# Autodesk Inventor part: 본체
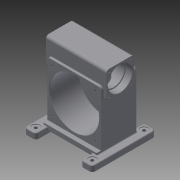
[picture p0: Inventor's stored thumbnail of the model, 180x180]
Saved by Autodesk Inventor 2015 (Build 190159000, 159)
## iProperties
Created: 2025-06
Part Number: 본체
Material: 일반
Document SubType Name: Modeling
Designer: User
Density: 1 g/cm^3
Appearance: 기본값
Author: User
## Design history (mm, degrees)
sketch "스케치4"
  geometry: L1 (-118, 110)-(-78, 110); L2 (-78, 110)-(-78, -110); L3 (-78, -110)-(-118, -110); L4 (-118, -110)-(-118, 110); L5 (78, 110)-(118, 110); L6 (118, 110)-(118, -110); L7 (118, -110)-(78, -110); L8 (78, -110)-(78, 110); 3 further points
  constraints: 16 end point, 4 parallel, 2 horizontal, 2 horizontal alignment, 2 midpoint, 2 perpendicular
  dimensions: "d1" = 40 distance of L2.end L3.end; "d2" = 220 distance of L1.end L2.end; "d3" = 118 distance from line of point (0, 0) L4; "d4" = 40 distance of L6.end L7.end; "d5" = 220 distance of L5.end L6.end; "d6" = 118 distance from line of point (0, 0) L6
extrude "돌출1" new body sketch "스케치4" distance "d7" = 20; taper "d8" = 0 deg
node "작업 평면2"
sketch "스케치5"
  geometry: L1 (93, 70)-(-93, 70); L2 (-93, 70)-(-93, -70); L3 (-93, -70)-(93, -70); L4 (93, -70)-(93, 70); L5 (93, 70)-(-93, -70); L6 (-93, 70)-(93, -70); 1 further point
  constraints: 12 end point, 2 midpoint, 2 parallel, 1 horizontal, 1 perpendicular
  dimensions: "d10" = 186 distance of L3.end L2.end; "d11" = 140 distance of L2.end L1.end
extrude "돌출2" join sketch "스케치5" distance "d12" = 206; taper "d13" = 0 deg
sketch "스케치6"
  geometry: L1 (-15, 206)-(171, 206); L2 (171, 206)-(171, 17); L3 (171, 17)-(-15, 17); L4 (-15, 17)-(-15, 206); 1 further point
  constraints: 8 end point, 2 parallel, 1 horizontal, 1 perpendicular
  dimensions: "d14" = 186 distance of L2.end L3.end; "d15" = 189 distance of L1.end L2.end
extrude "돌출3" cut sketch "스케치6" distance "d16" = 15; taper "d17" = 0 deg
sketch "스케치7"
  geometry: L1 (-15, 206)-(171, 206) reference; L2 (196, -10)-(156, -10) reference; C1 r 86 at (78, 113); 2 further points
  constraints: 1 centre point, 1 midpoint, 1 vertical alignment
  dimensions: "d18" = 172 diameter of C1; "d19" = 123 distance from line of L2 C1.centre
extrude "돌출4" cut sketch "스케치7" distance "d20" = 102; taper "d21" = 0 deg
sketch "스케치8"
  geometry: C1 r 86 at (0, 0) reference; C2 r 31 at (0, 0); 1 further point
  constraints: 1 centre point, 1 coincident
  dimensions: "d22" = 62 diameter of C2
extrude "돌출5" cut sketch "스케치8" distance "d23" = 16; taper "d24" = 0 deg
sketch "스케치9"
  geometry: C1 r 31 at (0, 0) reference; C2 r 27 at (0, 0); 1 further point
  constraints: 1 centre point, 1 coincident
  dimensions: "d25" = 54 diameter of C2
extrude "돌출6" cut sketch "스케치9" distance "d26" = 3; taper "d27" = 0 deg
fillet "모깎기1" dims "d28" = 3
fillet "모깎기2" dims "d29" = 1
chamfer "모따기1" distance "d30" = 1; stored, may be unused: second distance "d31" = 2, angle "d32" = 45 deg
chamfer "모따기2" distance "d33" = 1; stored, may be unused: second distance "d34" = 2, angle "d35" = 45 deg
sketch "스케치10"
  geometry: L1 (48, 271)-(-48, 271); L2 (-48, 271)-(-48, 175); L3 (-48, 175)-(48, 175); L4 (48, 175)-(48, 271); 2 further points
  constraints: 8 end point, 2 parallel, 1 horizontal, 1 midpoint, 1 perpendicular, 1 vertical alignment
  dimensions: "d36" = 96 distance of L3.end L2.end; "d37" = 96 distance of L2.end L1.end; "d38" = 271 distance from line of point (0, 0) L1
extrude "돌출7" join sketch "스케치10" stored distance "d39" = 210; taper "d40" = 0 deg
sketch "스케치11"
  geometry: C1 r 32 at (78, 113) reference; C2 r 86 at (78, 113); A1 r 86 centre (78, 113) between (9.502, 165) and (146.498, 165) reference; 1 further point
  constraints: 1 centre point, 1 coincident, 1 concentric
extrude "돌출8" cut sketch "스케치11" stored distance "d41" = 10; taper "d42" = 0 deg
sketch "스케치12"
  geometry: L1 (-271, 48)-(-271, -48) reference; C1 r 38.5 at (-223, 0); 1 further point
  constraints: 1 centre point, 1 horizontal alignment
  dimensions: "d43" = 77 diameter of C1; "d44" = 48 distance from line of C1.centre L1
extrude "돌출9" cut sketch "스케치12" stored distance "d45" = 10; taper "d46" = 0 deg
sketch "스케치13"
  geometry: C1 r 38.5 at (-223, 0) reference; C2 r 42.5 at (-223, 0); 1 further point
  constraints: 1 centre point, 1 coincident
  dimensions: "d47" = 85 diameter of C2
extrude "돌출10" cut sketch "스케치13" distance "d48" = 23; taper "d49" = 0 deg
fillet "모깎기3" dims "d50" = 1.1
chamfer "모따기3" distance "d51" = 1; stored, may be unused: second distance "d52" = 2, angle "d53" = 45 deg
sketch "스케치14"
  geometry: C1 r 38.5 at (223, 0) reference; C2 r 42.5 at (223, 0); 1 further point
  constraints: 1 centre point, 1 coincident
  dimensions: "d54" = 85 diameter of C2
extrude "돌출11" cut sketch "스케치14" distance "d55" = 23; taper "d56" = 0 deg
fillet "모깎기4" dims "d57" = 1.1
chamfer "모따기4" distance "d58" = 1; stored, may be unused: second distance "d59" = 2, angle "d60" = 45 deg
sketch "스케치15"
  geometry: L1 (3, 38)-(153, 38); L2 (153, 38)-(153, 188); L3 (153, 188)-(3, 188); L4 (3, 188)-(3, 38); L5 (3, 38)-(153, 188); L6 (153, 38)-(3, 188); C1 r 87 at (78, 113) reference; 1 further point
  constraints: 12 end point, 2 midpoint, 2 parallel, 1 horizontal, 1 perpendicular
  dimensions: "d61" = 150 distance of L3.end L2.end; "d62" = 150 distance of L2.end L1.end
hole "구멍1" sketch "스케치15" at (3, 188), (3, 38), (153, 38), (153, 188) diameter "d63" = 6.647; stored, may be unused: countersink angle "d67" = 90 deg, drill point angle "d69" = 118 deg; dims "d64" = 16, "d65" = 4, "d66" = 2, "d68" = 18
sketch "스케치16"
  geometry: L1 (-185, -38)-(-261, -38); L2 (-261, -38)-(-261, 38); L3 (-261, 38)-(-185, 38); L4 (-185, 38)-(-185, -38); L5 (-185, -38)-(-261, 38); L6 (-261, -38)-(-185, 38); C1 r 43.5 at (-223, 0) reference; 1 further point
  constraints: 12 end point, 2 midpoint, 2 parallel, 1 horizontal, 1 perpendicular
  dimensions: "d70" = 76 distance of L2.end L3.end; "d71" = 76 distance of L1.end L2.end
hole "구멍2" sketch "스케치16" at (-261, -38), (-185, -38), (-185, 38), (-261, 38) diameter "d72" = 4.917; stored, may be unused: countersink angle "d76" = 90 deg, drill point angle "d78" = 118 deg; dims "d73" = 12, "d74" = 4, "d75" = 2, "d77" = 14
sketch "스케치17"
  geometry: 2 further points
  dimensions: "d79" = 98 horizontal distance of point (0, 0) point (-98, -90); "d80" = 90 vertical distance of point (0, 0) point (-98, -90)
hole "구멍3" sketch "스케치17" at (-98, -90) diameter "d81" = 11; stored, may be unused: countersink angle "d85" = 90 deg, drill point angle "d87" = 118 deg; dims "d82" = 12, "d83" = 28, "d84" = 2, "d86" = 14
fillet "모깎기5" dims "d88" = 10
fillet "모깎기6" dims "d89" = 10
fillet "모깎기7" dims "d90" = 10
fillet "모깎기8" dims "d91" = 3
fillet "모깎기9" dims "d92" = 3
fillet "모깎기10" dims "d93" = 3
fillet "모깎기11" dims "d94" = 3
fillet "모깎기12" dims "d95" = 3
node "솔리드1"
mirror "대칭1"
mirror "대칭2"
mirror "대칭3"
